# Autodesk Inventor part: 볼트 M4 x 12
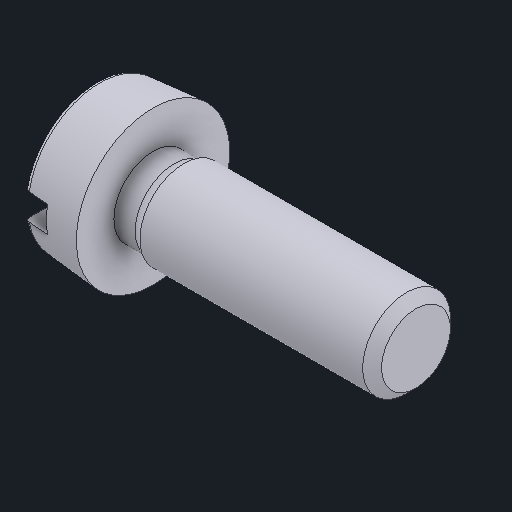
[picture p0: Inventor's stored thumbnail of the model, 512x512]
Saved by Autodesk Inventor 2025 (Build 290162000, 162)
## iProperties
Created: 2025-08
Part Number: 볼트 M4 x 12
Material: 강철, 연강
Description: 6각머리 태핑 나사
Document SubType Name: Modeling
Designer: infra005
Density: 7.85 g/cm^3
Appearance: 기본값
Author: jhkim
Sending System: Autodesk Inventor 2026
Preprocessor: ST-DEVELOPER v20.1
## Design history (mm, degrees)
feature "Solid1"
node "솔리드1"
